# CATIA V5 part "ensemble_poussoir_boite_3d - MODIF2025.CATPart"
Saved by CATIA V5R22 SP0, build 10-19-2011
Part number: ensemble poussoir boite
Bounding box of the stored display mesh (mm): x 22 to 187, y -63 to 111, z -1.5 to 31
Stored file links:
  D:\PER\CAO_PER_MODIF_2025\CAO_PER_pick&place_2024P\Sous_Ensemble_Boite\ensemble_poussoir_boite_3d - MODIF2025.CATPart
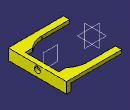
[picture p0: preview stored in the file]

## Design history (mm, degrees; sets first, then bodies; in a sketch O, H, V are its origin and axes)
Set1
  Plane1: type Offset, RefPlane face of Pocket3 from Sketch4.L1, Offset 16, reversed
Body1 (main body)
  Sketch1 on yz-plane, origin (0, 0, 0), H (0, 1, 0), V (0, 0, 1)
    line L1 (0, 0) -> (48, 0)
    line L2 (48, 0) -> (48, 31)
    line L3 (48, 31) -> (0, 31)
    line L4 (0, 31) -> (0, 0)
    point P1 (48, 0)
    point P2 (48, 31)
    point P3 (0, 31)
    distance P1 P2 = 31
    distance P2 P3 = 48
    horizontal: L1 H, L3 H
    vertical: L2 V, L4 V
  Pad1: profile Sketch1, direction (1, 0, 0), length 187
  Sketch2 on face of Pad1 from Sketch1.L4, origin (0, 0, 0), H (1, 0, 0), V (0, 0, 1)
    point P1 (15, 0)
    line L1 (15, 0) -> (173, 0)
    line L2 (173, 0) -> (173, 21)
    line L3 (173, 21) -> (15, 21)
    line L4 (15, 21) -> (15, 0)
    reference projected line E1 (0, 31) -> (187, 31) from edge [face of Pad1 from Sketch1.L4 | face of Pad1 from Sketch1.L3]
    reference projected line E2 (187, 31) -> (187, 0) from edge [face of Pad1 from Sketch1.L4 | end face of Pad1]
    reference projected line E3 (0, 31) -> (0, 0) from edge [start face of Pad1 | face of Pad1 from Sketch1.L4]
    distance L3 E1 = 10
    distance L2 E2 = 14
    distance L4 E3 = 15
    coincidence: P1 H
    horizontal: L1 H, L3 H
    vertical: L2 V, L4 V
  Pocket1: profile Sketch2, direction (0, 1, 0), through (limit type 3)
  Sketch3 on start face of Pad1, origin (0, 0, 0), H (0, -1, 0), V (0, 0, 1)
    line L1 (-41, 0) -> (-7, 0)
    line L2 (-7, 0) -> (-7, 31.5)
    line L3 (-41, 31.5) -> (-41, 0)
    point P2 (-7, 0)
    point P3 (-7, 49)
    point P4 (-41, 49)
    reference projected line E1 (0, 31) -> (0, 0) from edge [start face of Pad1 | face of Pad1 from Sketch1.L4]
    reference projected line E2 (-48, 0) -> (-48, 31) from edge [start face of Pad1 | face of Pad1 from Sketch1.L2]
    reference projected line E3 (0, 0) -> (-48, 0) from edge [start face of Pad1 | face of Pad1 from Sketch1.L1]
    point P5 (-7, 31.5)
    point P6 (-41, 31.5)
    arc A1 centre (-24, 25.5839) radius 18 from (-7, 31.5) to (-41, 31.5) ccw
    point P8 (-7, 31.5)
    point P9 (-41, 31.5)
    distance L2 E1 = 7
    distance L3 E2 = 7
    length L3 = 31.5
    radius A1 = 18
    distance P5 P2 = 31.5
    horizontal: L1 H
    vertical: L2 V, L3 V
    coincidence: E3 L1, L3 P6, L2 P5, P5 P8, P6 P9
  Pocket2: profile Sketch3, direction (1, 0, 0), up to face of Pocket1 from Sketch2.L4
  Sketch4 on face of Pad1 from Sketch1.L3, origin (0, 0, 31), H (1, 0, 0), V (0, 1, 0)
    point P1 (90, 24)
    line L1 (148, 8) -> (28, 8)
    line L2 (28, 40) -> (148, 40)
    point P3 (148, 8)
    point P4 (28, 8)
    arc A1 centre (148, 24) radius 16 from (148, 40) to (148, 8) cw
    arc A2 centre (28, 24) radius 16 from (28, 8) to (28, 40) cw
    point P7 (28, 24)
    reference projected line E1 (0, 48) -> (0, 0) from edge [start face of Pad1 | face of Pad1 from Sketch1.L3]
    distance L1 L2 = 32
    distance P3 P4 = 120
    radius A1 = 16
    radius A2 = 16
    distance P7 E1 = 28
    horizontal: L1 H, L2 H
    equidistance: L1 L2 P1
    fix: P1
  Pocket3: profile Sketch4, direction (0, 0, -1), through (limit type 3)
  Sketch5 on face of Pocket1 from Sketch2.L2, origin (173, 0, 0), H (0, 1, 0), V (0, 0, 1)
    circle A1 centre (24, 18) radius 4.25
    point P1 (24, 18)
    reference projected line E1 (48, 0) -> (48, 31) from edge [face of Pad1 from Sketch1.L2 | end face of Pad1]
    reference projected line E2 (0, 0) -> (48, 0) from edge [face of Pad1 from Sketch1.L1 | end face of Pad1]
    distance P1 E1 = 24
    radius A1 = 4.25
    distance P1 E2 = 18
  Pocket4: profile Sketch5, direction (1, 0, 0), length 7.5, opposite side through (limit type 3)
  Sketch6 on end face of Pad1, origin (187, 0, 0), H (0, 1, 0), V (0, 0, 1)
    circle A1 centre (24, 18) radius 9
    reference projected circle E1 centre (24, 18) radius 4.25 from Sketch5.A1
    radius A1 = 9
    concentricity: E1 A1
  Pocket5: profile Sketch6, direction (-1, 0, 0), length 9
  Sketch7 on face of Pad1 from Sketch1.L3, origin (0, 0, 31), H (1, 0, 0), V (0, 1, 0)
    point P2 (82, 0)
    line L1 (82, 48) -> (0, 48)
    point P3 (0, 48)
    point P4 (0, 48)
    line L2 (0, 48) -> (0, 0)
    point P5 (0, 0)
    line L3 (0, 0) -> (82, 0)
    reference projected line E1 (0, 48) -> (187, 48) from edge [face of Pad1 from Sketch1.L3 | face of Pad1 from Sketch1.L2]
    reference projected line E2 (0, 48) -> (0, 0) from edge [start face of Pad1 | face of Pad1 from Sketch1.L3]
    line L4 (82, 48) -> (82, 0)
    point P6 (82, 0)
    reference projected line E3 (187, 48) -> (187, 0) from edge [face of Pad1 from Sketch1.L3 | end face of Pad1]
    distance E3 L4 = 105
    horizontal: L1 H, L3 H
    coincidence: P5 H, E1 P4, P3 P4, L2 E2, P6 L3, P6 P2
    vertical: L2 V, L4 V
  Pocket6: profile Sketch7, direction (0, 0, -1), length 187
  Sketch8 on face of Pad1 from Sketch1.L4, origin (0, 0, 0), H (1, 0, 0), V (0, 0, 1)
    projected line E1 (187, 31) -> (187, 0) from edge [face of Pad1 from Sketch1.L4 | end face of Pad1]
    projected line E2 (173, 0) -> (187, 0) from edge [face of Pad1 from Sketch1.L1 | face of Pad1 from Sketch1.L4]
    projected line E3 (173, 0) -> (173, 21) from edge [face of Pad1 from Sketch1.L4 | face of Pocket1 from Sketch2.L2]
    projected line E4 (82, 31) -> (187, 31) from edge [face of Pad1 from Sketch1.L4 | face of Pad1 from Sketch1.L3]
    projected line E5 (82, 31) -> (82, 21) from edge [face of Pocket6 from Sketch7.L4 | face of Pad1 from Sketch1.L4]
    projected line E6 (173, 21) -> (82, 21) from edge [face of Pad1 from Sketch1.L4 | face of Pocket1 from Sketch2.L3]
  Pad2: profile Sketch8, direction (0, -1, 0), length 64
  Sketch9 on face of Pad1 from Sketch1.L2, origin (0, 48, 0), H (-1, 0, 0), V (0, 0, 1)
    projected line E1 (-173, 0) -> (-187, 0) from edge [face of Pad1 from Sketch1.L2 | face of Pad2]
    projected line E2 (-173, 0) -> (-173, 21) from edge [face of Pad2 | face of Pad1 from Sketch1.L2]
    projected line E3 (-187, 0) -> (-187, 31) from edge [face of Pad1 from Sketch1.L2 | face of Pad2]
    projected line E4 (-82, 31) -> (-187, 31) from edge [face of Pad2 | face of Pad1 from Sketch1.L2]
    projected line E5 (-173, 21) -> (-82, 21) from edge [face of Pad2 | face of Pad1 from Sketch1.L2]
    projected line E6 (-82, 31) -> (-82, 21) from edge [face of Pad1 from Sketch1.L2 | face of Pocket6 from Sketch7.L4]
  Pad3: profile Sketch9, direction (0, 1, 0), length 64
  Sketch10 on face of Pad3, origin (0, 0, 31), H (1, 0, 0), V (0, 1, 0)
    construction line L1 (105, 24) -> (-20.9536, 24)
    line L2 (105, -44) -> (-20.9536, -44)
    line L3 (-20.9536, 92) -> (105, 92)
    arc A1 centre (-20.9536, 24) radius 68 from (-20.9536, -44) to (-20.9536, 92) cw
    arc A2 centre (105, 24) radius 68 from (105, 92) to (105, -44) cw
    reference projected line E1 (82, 112) -> (187, 112) from edge [face of Pad3 | end face of Pad3]
    reference projected line E2 (187, -64) -> (82, -64) from edge [face of Pad3 | end face of Pad2]
    reference projected line E3 (82, 112) -> (187, 112) from edge [face of Pad3 | end face of Pad3]
    reference projected line E4 (187, 48) -> (187, 0) from edge [face of Pad3 | face of Pad3]
    distance E3 L3 = 20
    distance A2 E4 = 14
    horizontal: L1 H
    tangency: A1 L2, A2 L2, A1 L3, A2 L3
    symmetry: E1 E2 L1
  Pocket7: profile Sketch10, direction (0, 0, -1), through (limit type 3)
  Sketch11 on face of Pad3, origin (187, 0, 0), H (0, 1, 0), V (0, 0, 1)
    projected line E1 (-64, 0) -> (112, 0) from edge [face of Pad3 | face of Pad3]
    line L1 (112, 0) -> (112, -1.5)
    line L2 (112, -1.5) -> (-64, -1.5)
    line L3 (-64, -1.5) -> (-64, 0)
    distance E1 L2 = 1.5
    vertical: L1 V, L3 V
    horizontal: L2 H
  Pad4: profile Sketch11, direction (-1, 0, 0), length 14
  Sketch12 on face of Pad3, origin (0, 0, 31), H (1, 0, 0), V (0, 1, 0)
    projected line E1 (187, -64) -> (82, -64) from edge [face of Pad3 | face of Pad4]
    line L1 (187, -64) -> (187, -63)
    line L2 (187, -63) -> (82, -63)
    line L3 (82, -63) -> (82, -64)
    projected line E3 (82, 112) -> (187, 112) from edge [face of Pad3 | face of Pad4]
    line L4 (187, 112) -> (187, 111)
    line L5 (187, 111) -> (82, 111)
    line L6 (82, 111) -> (82, 112)
    distance L2 E1 = 1
    distance L5 E3 = 1
    vertical: L1 V, L3 V, L4 V, L6 V
    horizontal: L2 H, L5 H
  Pocket8: profile Sketch12, direction (0, 0, -1), through (limit type 3)
  Sketch13 on face of Pad2, origin (0, 0, 21), H (1, 0, 0), V (0, -1, 0)
    point P1 (173, -74)
    line L1 (173, -74) -> (133, -74)
    line L2 (133, -74) -> (133, 26)
    line L3 (133, 26) -> (173, 26)
    point P4 (173, 26)
    projected line E1 (173, 63) -> (173, -111) from edge [face of Pad4 | face of Pad4 from Sketch11.L2]
    projected line E2 (173, 26) -> (173, -74) from edge [face of Pad4 | face of Pad4 from Sketch11.L2]
    reference intersected line E3 through (0, -24) direction (-1, 0) from Plane1
    distance L3 L1 = 100
    distance L3 E3 = 50
    distance L2 E1 = 40
    horizontal: L1 H, L3 H
    vertical: L2 V
    coincidence: P1 E1, P4 E1
  Pocket9: profile Sketch13, direction (0, 0, 1), through (limit type 3)
  Sketch14 on face of Pad3, origin (0, 0, 31), H (1, 0, 0), V (0, 1, 0)
    point P1 (82, 111)
    line L1 (82, 111) -> (22, 111)
    point P2 (22, 111)
    line L2 (22, 111) -> (22, 92)
    point P3 (22, 92)
    line L3 (22, 92) -> (82, 92)
    point P4 (82, 92)
    line L4 (82, 92) -> (82, 111)
    reference projected line E1 (105, 92) -> (82, 92) from edge [face of Pad3 | face of Pocket7 from Sketch10.L3]
    reference projected line E2 (82, 111) -> (187, 111) from edge [face of Pad3 | face of Pocket8 from Sketch12.L5]
    reference projected line E3 (82, 40) -> (82, 112) from edge [face of Pad3 | face of Pad3]
    reference intersected line E5 through (0, 24) direction (1, 0) from Plane1
    point P7 (82, -44)
    point P8 (22, -44)
    line L5 (22, -44) -> (82, -44)
    reference intersected line E6 through (0, 24) direction (1, 0) from Plane1
    point P11 (22, -44)
    point P12 (22, -63)
    line L6 (22, -63) -> (22, -44)
    reference intersected line E7 through (0, 24) direction (1, 0) from Plane1
    point P15 (22, -63)
    point P16 (82, -63)
    line L7 (82, -63) -> (22, -63)
    reference intersected line E8 through (0, 24) direction (1, 0) from Plane1
    point P19 (82, -63)
    point P20 (82, -44)
    line L8 (82, -44) -> (82, -63)
    distance L4 L2 = 60
    horizontal: L1 H, L3 H
    vertical: L2 V, L4 V
    coincidence: L3 E1, L1 E2, L4 E3, P7 P20, P8 P11, P12 P15, P16 P19
    symmetry: P4 P7 E5, P3 P8 E5, L3 L5 E5, P3 P11 E6, P2 P12 E6, L2 L6 E6, P2 P15 E7, P1 P16 E7, L1 L7 E7, P1 P19 E8, P4 P20 E8, L4 L8 E8
  Pad5: profile Sketch14, direction (0, 0, -1), length 10
  Chamfer1: length 1, angle 45, on edge [face of Pad4 | face of Pad5]; edge [face of Pad5 | face of Pad4]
